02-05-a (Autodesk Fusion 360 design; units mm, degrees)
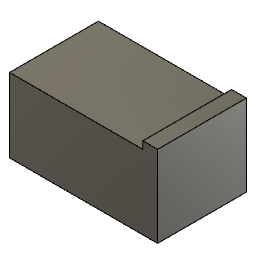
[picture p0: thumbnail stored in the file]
sketch "スケッチ1" plane through (0, 0, 0) normal (0, 0, 1) x axis (1, 0, 0)
  line L1 (-50, 25) -> (50, 25)
  line L2 (-50, -25) -> (-50, 25)
  line L3 (50, -25) -> (-50, -25)
  line L4 (50, 25) -> (50, -25)
  line L5 (-50, -25) -> (50, 25)
  line L6 (50, -25) -> (-50, 25)
  point P6 (0, 0)
  point P1 (0, 0)
  point P2 (50, 25)
  point P3 (-50, 25)
  point P5 (50, -25)
  horizontal L1
  perpendicular L1 L2
  parallel L1 L3
  parallel L2 L4
  coincident L5 P6
  coincident L6 P6
  coincident P1 P6
  dimension "d1" distance P2 P3 = 100
  dimension "d2" distance P2 P5 = 50
extrude "押し出し1" new body sketch "スケッチ1" profile of L1 L2 L3 L4 distance 60
sketch "スケッチ2" plane through (0, 25, 0) normal (0, 1, 0) x axis (-1, 0, 0)
  line L1 (50, 30) -> (50, -30)
  line L2 (-50, 30) -> (50, 30)
  line L3 (-50, -30) -> (-50, 30)
  line L4 (50, -30) -> (-50, -30)
  line L5 (-50, -30) -> (-40, -30)
  line L6 (-50, 30) -> (-50, -30)
  line L7 (-40, 30) -> (-50, 30)
  line L8 (-40, -30) -> (-40, 30)
  point P5 (-50, -30)
  point P7 (-50, -30)
  point P4 (-50, 30)
  point P8 (-50, 30)
  point P6 (-40, -30)
  horizontal L5
  vertical L6
  horizontal L7
  vertical L8
  coincident P5 P7
  coincident P4 P8
  dimension "d5" distance P6 P7 = 10
extrude "押し出し2" add sketch "スケッチ2" profile of L2 L3 L4 L5 L6 L7 L8 along normal blind 5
